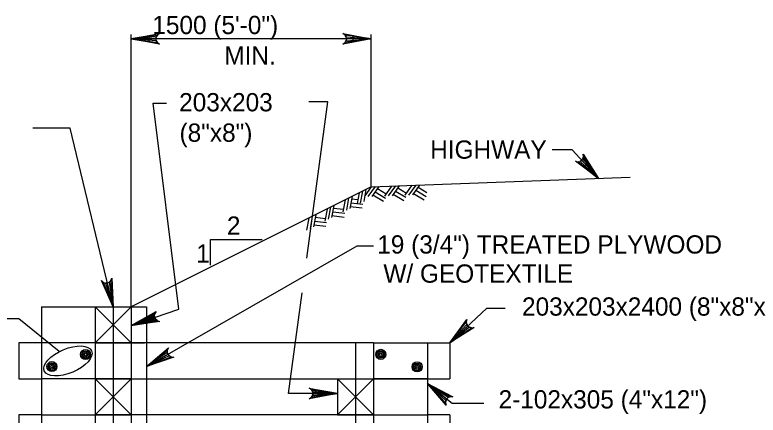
# Model space of a CAD drawing. Extents: x 0 to 36.3, y -44 to 0.
# Drawn here: x 18.454 to 23.344, y -14.638 to -12.009 of the extents above; entities that cross this region are included whole.
import ezdxf

# ---------------------------------------------------------------- set-up
doc = ezdxf.new("R2010")
doc.units = 0
for name, color, linetype in [('3', 7, 'Continuous'), ('5', 7, 'Continuous'), ('52', 7, 'Continuous')]:
    doc.layers.add(name, color=color, linetype=linetype)

msp = doc.modelspace()

# ---------------------------------------------------------------- linework, layer by layer
at = {"layer": '3'}
for p, q in [((20.7982, -13.1382), (22.5018, -13.0758)), ((20.7982, -13.1382), (19.2192, -13.9278)), ((20.7982, -13.1382), (20.7557, -13.1982)), ((20.8235, -13.1373), (20.777, -13.2027)), ((20.8487, -13.1364), (20.8022, -13.2018)), ((20.8389, -13.1502), (20.8957, -13.1847)), ((20.9321, -13.1334), (20.8856, -13.1988)), ((20.9572, -13.1326), (20.9108, -13.1979)), ((20.9824, -13.1317), (20.9359, -13.197)), ((20.9727, -13.1454), (21.0294, -13.1798)), ((21.0658, -13.1287), (21.0193, -13.194)), ((21.0911, -13.1277), (21.0446, -13.1932)), ((21.1163, -13.1268), (21.0697, -13.1922)), ((21.1065, -13.1406), (21.1632, -13.175)), ((20.6722, -13.2013), (20.6572, -13.2802)), ((20.7188, -13.178), (20.7057, -13.2474)), ((20.7413, -13.1667), (20.7263, -13.2455)), ((20.7637, -13.1553), (20.7488, -13.2342)), ((20.8096, -13.1913), (20.8781, -13.2329)), ((20.8242, -13.1707), (20.8927, -13.2123)), ((20.9434, -13.1865), (21.0119, -13.2281)), ((20.958, -13.166), (21.0265, -13.2075)), ((21.0772, -13.1817), (21.1457, -13.2233)), ((21.0918, -13.1612), (21.1603, -13.2027)), ((20.6272, -13.2241), (20.6122, -13.3029)), ((20.6497, -13.2127), (20.6348, -13.2916)), ((20.6643, -13.2427), (20.7439, -13.2518)), ((20.669, -13.2179), (20.7103, -13.2226)), ((20.5077, -13.2844), (20.4928, -13.3632)), ((20.5302, -13.2731), (20.5152, -13.3519)), ((20.5527, -13.2617), (20.5377, -13.3405)), ((20.5495, -13.2782), (20.6155, -13.2858)), ((20.6597, -13.2675), (20.7392, -13.2766)), ((20.3882, -13.3447), (20.3732, -13.4236)), ((20.4107, -13.3334), (20.3957, -13.4123)), ((20.4332, -13.322), (20.4183, -13.4009)), ((20.43, -13.3386), (20.496, -13.3462)), ((20.5402, -13.3279), (20.6197, -13.337)), ((20.5448, -13.3031), (20.6244, -13.3122)), ((20.4207, -13.3882), (20.5002, -13.3973)), ((20.4253, -13.3634), (20.5049, -13.3725)), ((18.6286, -13.9278), (18.9829, -13.9278)), ((18.6286, -13.9278), (18.6286, -16.9987)), ((18.9829, -13.9278), (18.9829, -14.1641)), ((18.9829, -14.1641), (19.2192, -13.9278)), ((18.9829, -13.9278), (19.2192, -14.1641)), ((18.9829, -13.9278), (19.3198, -13.9278)), ((19.101, -13.9278), (19.101, -16.9439)), ((19.2192, -13.9278), (19.2192, -16.9987)), ((19.3198, -13.9278), (19.3198, -16.5576)), ((18.6286, -14.1641), (18.4809, -14.1641)), ((18.4809, -14.1641), (18.4809, -14.4002)), ((19.2192, -14.1641), (18.6286, -14.1641)), ((19.2192, -14.1641), (18.9829, -14.1641)), ((18.9829, -14.1641), (18.9829, -16.9987)), ((18.9829, -14.1641), (19.2192, -14.1641)), ((20.8137, -14.1641), (19.2192, -14.1641)), ((19.2192, -14.1641), (19.3077, -14.1641)), ((20.6955, -14.1641), (20.6955, -15.7248)), ((20.8137, -14.1641), (21.3156, -14.1641)), ((20.8137, -14.1641), (20.8137, -16.563)), ((21.168, -14.1641), (21.168, -15.8176)), ((21.3156, -14.1641), (21.3156, -14.4002)), ((18.4809, -14.4002), (18.6286, -14.4002)), ((19.2192, -14.4002), (18.6286, -14.4002)), ((18.9829, -14.4002), (19.2192, -14.4002)), ((18.9829, -14.4002), (19.2192, -14.6365)), ((18.9829, -14.6365), (19.2192, -14.4002)), ((18.9829, -14.4002), (18.9829, -14.6365)), ((19.2192, -14.4002), (20.8137, -14.4002)), ((19.2192, -14.4002), (19.2192, -14.6365)), ((20.5774, -14.4002), (20.5774, -14.6365)), ((20.5774, -14.6365), (20.8137, -14.4002)), ((20.5774, -14.4002), (20.8137, -14.6365)), ((20.5774, -14.4002), (20.8137, -14.4002)), ((20.8137, -14.4002), (20.8137, -14.6365)), ((21.168, -14.4002), (20.8137, -14.4002)), ((20.8137, -14.4002), (21.168, -14.4002)), ((21.168, -14.4002), (21.3156, -14.4002)), ((21.168, -14.4002), (21.168, -16.9987)), ((18.4809, -14.6365), (18.4809, -14.8727)), ((18.6286, -14.6365), (18.4809, -14.6365)), ((18.6286, -14.6365), (18.9829, -14.6365)), ((19.2192, -14.6365), (18.9829, -14.6365)), ((18.9829, -14.6365), (19.2192, -14.6365)), ((20.8137, -14.6365), (18.9829, -14.6365)), ((20.5774, -14.6365), (20.8137, -14.6365)), ((20.8137, -14.6365), (21.168, -14.6365)), ((21.3156, -14.6365), (21.168, -14.6365)), ((21.3156, -14.6365), (21.3156, -14.8727))]:
    msp.add_line(p, q, dxfattribs=at)
for centre, radius in [((18.9192, -14.2403), 0.0333), ((18.9192, -14.2403), 0.025), ((18.9192, -14.2403), 0.0167), ((20.8609, -14.2391), 0.0333), ((20.8609, -14.2391), 0.025), ((20.8609, -14.2391), 0.0167), ((18.9192, -14.2403), 0.00833), ((20.8609, -14.2391), 0.00833), ((18.6977, -14.3196), 0.0333), ((18.6977, -14.3196), 0.025), ((18.6977, -14.3196), 0.0167), ((18.6977, -14.3196), 0.00833), ((21.1004, -14.3217), 0.0333), ((21.1004, -14.3217), 0.025), ((21.1004, -14.3217), 0.0167), ((21.1004, -14.3217), 0.00833)]:
    msp.add_circle(centre, radius, dxfattribs=at)
at = {"layer": '5'}
for p, q in [((19.2192, -13.9278), (19.2192, -12.1367)), ((20.7982, -12.1662), (19.2192, -12.1662)), ((20.7982, -13.1382), (20.7982, -12.1367)), ((22.1197, -12.8954), (21.9889, -12.8954)), ((22.294, -13.0834), (22.1197, -12.8954)), ((19.7409, -13.484), (20.0815, -13.484)), ((19.7409, -13.653), (19.7409, -13.484)), ((19.3198, -14.3193), (20.7067, -13.527)), ((20.7067, -13.527), (20.8139, -13.527)), ((21.3156, -14.1641), (21.5599, -13.9348)), ((21.5599, -13.9348), (21.6799, -13.9348)), ((21.168, -14.4305), (21.3307, -14.5597)), ((21.3307, -14.5597), (21.5388, -14.5597))]:
    msp.add_line(p, q, dxfattribs=at)
for points in [[(19.2192, -12.1662), (19.4056, -12.1313), (19.3912, -12.1412), (19.3838, -12.1537), (19.3817, -12.1662), (19.3838, -12.1787), (19.3912, -12.1913), (19.4056, -12.2012), (19.2192, -12.1662), (19.3912, -12.1913), (19.3838, -12.1787), (19.2192, -12.1662), (19.3817, -12.1662), (19.3838, -12.1537), (19.2192, -12.1662), (19.3912, -12.1412)], [(20.7982, -12.1662), (20.6118, -12.2012), (20.6262, -12.1913), (20.6336, -12.1787), (20.6357, -12.1662), (20.6336, -12.1537), (20.6262, -12.1412), (20.6118, -12.1313), (20.7982, -12.1662), (20.6262, -12.1412), (20.6336, -12.1537), (20.7982, -12.1662), (20.6357, -12.1662), (20.6336, -12.1787), (20.7982, -12.1662), (20.6262, -12.1913)], [(19.101, -13.9278), (18.8171, -12.7537), (18.5725, -12.7537)], [(22.294, -13.0834), (22.1417, -12.9704), (22.1587, -12.9742), (22.1729, -12.9712), (22.1835, -12.9642), (22.1913, -12.9542), (22.1954, -12.9402), (22.1929, -12.9229), (22.294, -13.0834), (22.1954, -12.9402), (22.1913, -12.9542), (22.294, -13.0834), (22.1835, -12.9642), (22.1729, -12.9712), (22.294, -13.0834), (22.1587, -12.9742)], [(19.101, -13.9278), (19.0233, -13.7549), (19.0362, -13.7665), (19.0502, -13.7707), (19.0628, -13.7699), (19.0744, -13.7649), (19.0848, -13.7547), (19.0912, -13.7384), (19.101, -13.9278), (19.0848, -13.7547), (19.0744, -13.7649), (19.101, -13.9278), (19.0628, -13.7699), (19.0502, -13.7707), (19.101, -13.9278), (19.0362, -13.7665)], [(18.7454, -14.2215), (18.4798, -14.0069), (18.1295, -14.0069)], [(21.3156, -14.1641), (21.4276, -14.0111), (21.4239, -14.0282), (21.4271, -14.0423), (21.4341, -14.0529), (21.4442, -14.0606), (21.4582, -14.0646), (21.4754, -14.062), (21.3156, -14.1641), (21.4582, -14.0646), (21.4442, -14.0606), (21.3156, -14.1641), (21.4341, -14.0529), (21.4271, -14.0423), (21.3156, -14.1641), (21.4239, -14.0282)], [(19.3198, -14.3193), (19.4643, -14.1965), (19.4568, -14.2122), (19.4566, -14.2268), (19.4609, -14.2387), (19.469, -14.2485), (19.4816, -14.2557), (19.499, -14.2572), (19.3198, -14.3193), (19.4816, -14.2557), (19.469, -14.2485), (19.3198, -14.3193), (19.4609, -14.2387), (19.4566, -14.2268), (19.3198, -14.3193), (19.4568, -14.2122)], [(21.168, -14.4305), (21.3358, -14.519), (21.3183, -14.5178), (21.3047, -14.5231), (21.2952, -14.5315), (21.2892, -14.5427), (21.2873, -14.557), (21.2922, -14.5737), (21.168, -14.4305), (21.2873, -14.557), (21.2892, -14.5427), (21.168, -14.4305), (21.2952, -14.5315), (21.3047, -14.5231), (21.168, -14.4305), (21.3183, -14.5178)]]:
    msp.add_lwpolyline(points, dxfattribs=at)
for points in [[(19.3373, -12.1859), (19.3373, -12.1465), (19.2192, -12.1662)], [(20.6802, -12.1859), (20.6802, -12.1465), (20.7982, -12.1662)], [(22.2281, -12.9834), (22.1992, -13.0102), (22.2939, -13.0834)], [(21.2723, -14.4882), (21.2478, -14.519), (21.1676, -14.4301)]]:
    msp.add_lwpolyline(points, close=True, dxfattribs=at)
msp.add_ellipse((18.8031, -14.2826), major_axis=(0.1556, 0.0657), ratio=0.473013, dxfattribs=at)
at = {"layer": '52'}
for points in [[(19.2192, -14.0499), (19.5325, -13.9429), (19.3632, -12.5881), (19.4523, -12.5881)], [(20.3738, -13.6072), (20.5124, -12.5792), (20.3877, -12.5792)], [(20.5774, -14.4956), (20.254, -14.4956), (20.343, -13.8353)], [(19.2192, -14.0499), (19.3843, -13.9566), (19.3791, -13.9636), (19.3739, -13.9707), (19.3724, -13.9778), (19.371, -13.9849), (19.372, -13.9911), (19.373, -13.9974), (19.376, -14.003), (19.379, -14.0085), (19.3846, -14.0133), (19.3901, -14.018), (19.3985, -14.0204), (19.4069, -14.0228), (19.2192, -14.0499), (19.3985, -14.0204), (19.3901, -14.018), (19.2192, -14.0499), (19.3846, -14.0133), (19.379, -14.0085), (19.2192, -14.0499), (19.376, -14.003), (19.373, -13.9974), (19.2192, -14.0499), (19.372, -13.9911), (19.371, -13.9849), (19.2192, -14.0499), (19.3724, -13.9778), (19.3739, -13.9707), (19.2192, -14.0499), (19.3791, -13.9636)], [(20.5774, -14.4956), (20.391, -14.5305), (20.3982, -14.5255), (20.4054, -14.5206), (20.4091, -14.5143), (20.4128, -14.5081), (20.4138, -14.5018), (20.4149, -14.4956), (20.4138, -14.4893), (20.4128, -14.4831), (20.4091, -14.4768), (20.4054, -14.4706), (20.3982, -14.4656), (20.391, -14.4606), (20.5774, -14.4956), (20.3982, -14.4656), (20.4054, -14.4706), (20.5774, -14.4956), (20.4091, -14.4768), (20.4128, -14.4831), (20.5774, -14.4956), (20.4138, -14.4893), (20.4149, -14.4956), (20.5774, -14.4956), (20.4138, -14.5018), (20.4128, -14.5081), (20.5774, -14.4956), (20.4091, -14.5143), (20.4054, -14.5206), (20.5774, -14.4956), (20.3982, -14.5255)]]:
    msp.add_lwpolyline(points, dxfattribs=at)

# ---------------------------------------------------------------- texts
at = {"layer": '5'}
for s, p in [('1500 (5\'-0")', (19.3582, -12.1352)), ('MIN.', (19.8317, -12.3353)), ('203x203', (19.5347, -12.6426)), ('(8"x8")', (19.5372, -12.8427)), ('HIGHWAY', (21.1862, -12.9538)), ('2', (19.8487, -13.4532)), ('19 (3/4") TREATED PLYWOOD', (20.838, -13.5771)), ('1', (19.6467, -13.6363)), ('W/ GEOTEXTILE', (20.8786, -13.7683)), ('203x203x2400 (8"x8"x8\'-0")', (21.7904, -13.9849)), ('2-102x305 (4"x12")', (21.6363, -14.5948))]:
    msp.add_text(s, height=0.12, dxfattribs=at).set_placement(p)

doc.saveas('drawing.dxf')
